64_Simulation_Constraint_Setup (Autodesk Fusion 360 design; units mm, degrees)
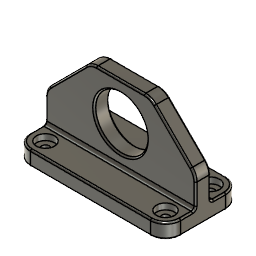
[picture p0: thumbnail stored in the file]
part number: 2026-07-20-13-25-26-316
sketch "Sketch1" plane through (0, 0, 0) normal (0, 1, 0) x axis (1, 0, 0)
  line L1 (-50, 25) -> (50, 25)
  line L2 (-50, -25) -> (-50, 25)
  line L3 (50, -25) -> (-50, -25)
  line L4 (50, 25) -> (50, -25)
  line L5 (-50, -25) -> (50, 25)
  line L6 (50, -25) -> (-50, 25)
  point P6 (0, 0)
  point P1 (0, 0)
  point P4 (-50, -25)
  point P5 (50, -25)
  point P3 (-50, 25)
  horizontal L1
  perpendicular L1 L2
  parallel L1 L3
  parallel L2 L4
  coincident L5 P6
  coincident L6 P6
  coincident P1 P6
  dimension "d2" distance P4 P5 = 100
  dimension "d3" distance P3 P4 = 50
extrude "Extrude1" new body sketch "Sketch1" profile of L1 L2 L3 L4 distance 10
sketch "Sketch2" plane through (0, 0, -25) normal (0, 0, -1) x axis (1, 0, 0)
  line L1 (-50, -5) -> (-50, 5)
  line L2 (50, -5) -> (-50, -5)
  line L3 (50, 5) -> (50, -5)
  line L4 (-50, 5) -> (50, 5)
  line L5 (-50, -25) -> (50, -25)
  line L6 (-50, 25) -> (-50, -25)
  line L7 (50, 25) -> (-50, 25)
  line L8 (50, -25) -> (50, 25)
  line L9 (-50, 25) -> (50, -25)
  line L10 (50, 25) -> (-50, -25)
  point P10 (0, 0)
  point P1 (0, 0)
  point P5 (50, 5)
  point P7 (-50, -25)
  point P8 (-50, 25)
  horizontal L5
  perpendicular L5 L6
  parallel L5 L7
  parallel L6 L8
  coincident L9 P10
  coincident L10 P10
  coincident P1 P10
  coincident P5 L8
  dimension "d6" distance P7 P8 = 50
extrude "Extrude2" add sketch "Sketch2" profile of L1 L2 L3 L4 L5 L6 L7 L8 along normal blind 10
chamfer "Chamfer1" sketch "Sketch2" distance 30
sketch "Sketch3" plane through (0, -5, 0) normal (0, -1, 0) x axis (1, 0, 0)
  line L1 (20, 25) -> (50, -5)
  line L2 (-20, 25) -> (20, 25)
  line L3 (-50, -5) -> (-20, 25)
  line L4 (-50, -25) -> (-50, -5)
  line L5 (50, -25) -> (-50, -25)
  line L6 (50, -5) -> (50, -25)
  circle C1 centre (0, 0) radius 17.5
  point P1 (0, 0)
  point P8 (0, 0)
  coincident P1 P8
  dimension "d10" diameter C1 = 35
extrude "Extrude3" cut sketch "Sketch3" profile of C1 no distance stored
fillet "Fillet1" radius 10
fillet "Fillet2" radius 10
sketch "Sketch4" plane through (0, 0, -25) normal (0, 0, 1) x axis (-1, 0, 0)
  line L1 (50, -5) -> (50, -15)
  line L2 (-50, -5) -> (50, -5)
  line L3 (-50, -15) -> (-50, -5)
  line L4 (40, -25) -> (-40, -25)
  line L5 (-40, 25) -> (40, 25)
  line L6 (-50, 5) -> (-50, 15)
  line L7 (50, 5) -> (-50, 5)
  line L8 (50, 15) -> (50, 5)
  arc A1 centre (40, -15) radius 10 clockwise from (50, -15) to (40, -25)
  arc A2 centre (-40, -15) radius 10 clockwise from (-40, -25) to (-50, -15)
  arc A3 centre (40, 15) radius 10 clockwise from (40, 25) to (50, 15)
  arc A4 centre (-40, 15) radius 10 clockwise from (-50, 15) to (-40, 25)
  point P9 (-40, -15)
  point P18 (-40, -15)
  point P4 (40, -15)
  point P19 (40, -15)
  point P12 (40, 15)
  point P20 (40, 15)
  point P15 (-40, 15)
  point P21 (-40, 15)
  coincident P9 P18
  coincident P4 P19
  coincident P12 P20
  coincident P15 P21
hole "Hole1" sketch "Sketch2" HoleDiameter 5 TipAngle 118 CBDepth 4 CBDiameter 12
fillet "Fillet3" radius 2
fillet "Fillet4" radius 1
chamfer "Chamfer2" sketch "Sketch2" distance 1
